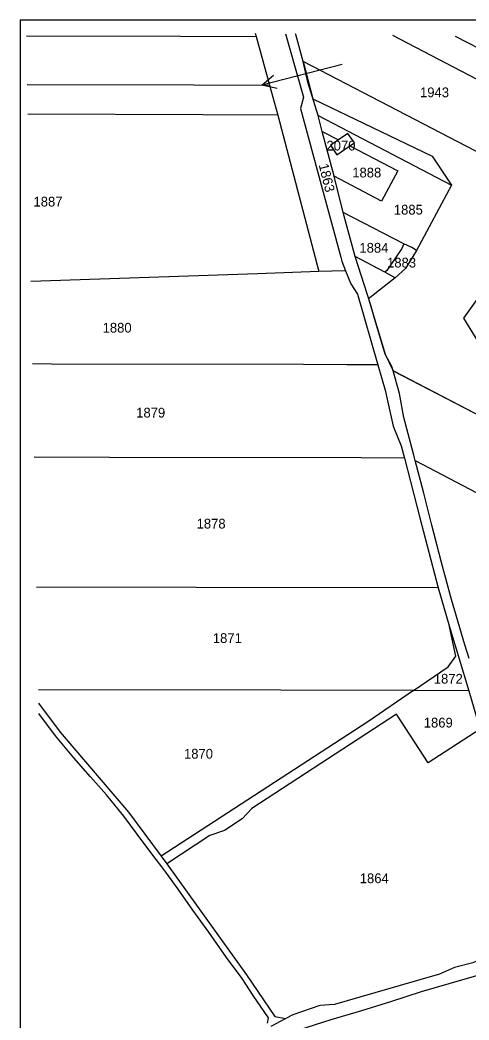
# Model space of a CAD drawing. Extents: x -584305 to -582773, y -1166873 to -1164754.
# Drawn here: x -584305 to -583983, y -1165491 to -1164773 of the extents above; entities that cross this region are included whole.
import ezdxf

# ---------------------------------------------------------------- set-up
doc = ezdxf.new("R2010")
doc.units = 0
for name, color, linetype in [('37', 7, 'Continuous'), ('_Rám HC11-R', 7, 'Continuous'), ('Hranice parcel', 7, 'Continuous'), ('Parcelní čísla', 7, 'Continuous')]:
    doc.layers.add(name, color=color, linetype=linetype)

msp = doc.modelspace()

# ---------------------------------------------------------------- linework, layer by layer
at = {"layer": '37'}
msp.add_line((-584073.78, -1164805.07), (-584131.38, -1164819.91), dxfattribs=at)
msp.add_lwpolyline([(-584120.54, -1164822.24), (-584131.38, -1164819.91), (-584123.02, -1164812.64)], dxfattribs=at)
at = {"layer": '_Rám HC11-R'}
msp.add_lwpolyline([(-582820.03, -1166873.12), (-582820.03, -1164773.12), (-584305.03, -1164773.12), (-584305.03, -1166873.12), (-582820.03, -1166873.12)], dxfattribs=at)
msp.add_lwpolyline([(-583928.98, -1165081.35), (-583986.49, -1164987.28), (-583967.99, -1164961.13), (-583954.85, -1164923.82), (-583942.36, -1164931.66), (-583924.13, -1164896.6), (-583941.58, -1164886.27), (-584101.83, -1164802.98), (-584094.81, -1164829.69), (-584009.27, -1164870.93), (-583995.35, -1164891.63), (-584020.43, -1164938.66), (-584028.48, -1164951.62), (-584035.7, -1164958.26), (-584055.06, -1164973.28), (-584042.99, -1165013.09), (-584037.3, -1165024.95)], close=True, dxfattribs=at)
at = {"layer": 'Hranice parcel'}
for p, q in [((-584136.29, -1164782.6), (-584135.64, -1164784.94)), ((-584135.64, -1164784.94), (-584126.01, -1164819.84)), ((-583956.67, -1164826.46), (-584037.5, -1164784.25)), ((-583947.23, -1164808.23), (-583992.46, -1164785)), ((-584126.01, -1164819.84), (-584120.06, -1164841.33)), ((-584120.06, -1164841.33), (-584090.48, -1164953.81)), ((-584088.14, -1164853.24), (-584091.16, -1164841.68)), ((-584079.67, -1164885.17), (-584088.14, -1164853.24)), ((-584088.14, -1164853.24), (-584076.59, -1164859.25)), ((-584073.2, -1164911.26), (-584079.67, -1164885.17)), ((-584064.56, -1164942.96), (-584073.2, -1164911.26)), ((-584029.68, -1164933.86), (-584073.2, -1164911.26)), ((-584043.31, -1164954.22), (-584064.56, -1164942.96)), ((-584071.34, -1164953.16), (-584090.48, -1164953.81)), ((-583928.98, -1165081.35), (-584037.3, -1165024.95)), ((-584004.96, -1165180.89), (-583996.84, -1165208.83)), ((-583996.84, -1165208.83), (-583983.04, -1165254.67)), ((-583983.04, -1165254.67), (-584022.77, -1165254.58)), ((-584203.2, -1165381.2), (-584207.26, -1165375.81)), ((-584203.74, -1165373.5), (-584199.68, -1165378.89)), ((-584114.38, -1165490.11), (-584125.04, -1165495.82))]:
    msp.add_line(p, q, dxfattribs=at)
for points in [[(-584114.4, -1164782.96), (-584112.02, -1164791.38), (-584101.48, -1164828.6), (-584103.83, -1164836.55), (-584088.97, -1164891.37), (-584074.9, -1164943.28), (-584074.11, -1164946.18), (-584071.34, -1164953.16)], [(-584101.83, -1164802.98), (-584107.21, -1164783.62), (-584107.33, -1164783.08)], [(-584300.45, -1164784.58), (-584189.89, -1164784.82), (-584135.64, -1164784.94)], [(-584091.16, -1164841.68), (-584098.46, -1164817.69), (-584101.83, -1164802.98)], [(-583924.13, -1164896.6), (-583941.58, -1164886.27), (-584101.83, -1164802.98)], [(-584299.81, -1164819.45), (-584180.12, -1164819.72), (-584126.01, -1164819.84)], [(-584120.06, -1164841.33), (-584173.88, -1164841.17), (-584299.42, -1164840.8)], [(-584091.16, -1164841.68), (-583995.35, -1164891.63), (-584020.43, -1164938.66)], [(-584068.32, -1164863.56), (-584065.1, -1164861.38), (-584069.75, -1164854.62), (-584076.59, -1164859.25)], [(-584076.59, -1164859.25), (-584082.28, -1164863.1), (-584077.69, -1164869.91), (-584068.32, -1164863.56)], [(-584068.32, -1164863.56), (-584033.99, -1164881.43), (-584045.57, -1164903.16), (-584079.67, -1164885.17)], [(-584029.68, -1164933.86), (-584030.98, -1164937.12), (-584041.73, -1164953.04), (-584043.31, -1164954.22)], [(-584020.43, -1164938.66), (-584023.92, -1164936.53), (-584029.68, -1164933.86)], [(-584020.43, -1164938.66), (-584028.48, -1164951.62), (-584035.7, -1164958.26), (-584043.31, -1164954.22)], [(-584037.3, -1165024.95), (-584038.16, -1165021.95), (-584042.99, -1165013.09), (-584050.52, -1164988.21), (-584053.61, -1164977.12), (-584064.56, -1164942.96)], [(-584090.48, -1164953.81), (-584134.71, -1164955.31), (-584297.22, -1164960.82)], [(-584071.34, -1164953.16), (-584067.63, -1164962.48), (-584062.83, -1164970.07), (-584048.18, -1165020.65)], [(-584048.18, -1165020.65), (-584070.46, -1165020.6), (-584101.61, -1165020.53), (-584282.43, -1165020.13), (-584296.13, -1165020.1)], [(-584048.18, -1165020.65), (-584042.91, -1165038.81), (-584037.18, -1165064.8), (-584031.46, -1165078.76), (-584029.16, -1165087.65)], [(-584021.34, -1165089.39), (-584022.33, -1165085.67), (-584029.5, -1165058.59), (-584032.63, -1165041.29), (-584037.3, -1165024.95)], [(-584029.16, -1165087.65), (-584060.23, -1165087.58), (-584240.73, -1165087.18), (-584294.91, -1165087.06)], [(-584029.16, -1165087.65), (-584018.01, -1165130.6), (-584004.96, -1165180.89)], [(-583982.63, -1165231.56), (-583985.75, -1165221.62), (-583995.35, -1165189.21), (-584002.45, -1165162.55), (-584009.56, -1165135.88), (-584015.15, -1165112.74), (-584021.34, -1165089.39)], [(-584021.34, -1165089.39), (-583953, -1165125.34), (-583904.11, -1165151.07)], [(-584004.96, -1165180.89), (-584178.59, -1165180.51), (-584293.2, -1165180.26)], [(-584022.77, -1165254.58), (-583997.85, -1165237.48), (-583992.24, -1165229.99), (-583996.84, -1165208.83)], [(-584022.77, -1165254.58), (-584117.85, -1165254.37), (-584291.84, -1165253.99)], [(-584022.77, -1165254.58), (-584055.51, -1165277.05), (-584203.74, -1165373.5)], [(-583983.04, -1165254.67), (-583977.35, -1165273.76), (-583974.84, -1165282.18)], [(-584291.66, -1165263.71), (-584276.18, -1165284.38), (-584227.24, -1165341.86), (-584203.74, -1165373.5)], [(-584207.26, -1165375.81), (-584216.08, -1165364.12), (-584230.46, -1165344.81), (-584242.87, -1165329.46), (-584254.33, -1165316.55), (-584266.48, -1165302.89), (-584279.48, -1165286.98), (-584291.53, -1165271.1)], [(-583974.84, -1165282.18), (-584012.07, -1165306.46), (-584034.84, -1165271.61), (-584138.63, -1165339.21), (-584145.7, -1165346.69), (-584158.2, -1165355.08), (-584168.81, -1165358.7), (-584199.68, -1165378.89)], [(-583974.84, -1165282.18), (-583954.94, -1165348.93), (-583952.24, -1165368.22), (-583945.43, -1165383.61), (-583944.47, -1165391.31), (-583943.78, -1165404.8), (-583949.92, -1165432.02), (-583955.76, -1165438.7), (-583979.99, -1165450.08), (-583993.12, -1165453.3), (-584003.91, -1165458.08), (-584032.27, -1165466.39), (-584079.46, -1165479.88), (-584089.8, -1165480.66), (-584109.32, -1165487.31), (-584114.38, -1165490.11)], [(-584199.68, -1165378.89), (-584142.41, -1165458.77), (-584122.2, -1165488.62), (-584114.38, -1165490.11)], [(-584127.54, -1165493.29), (-584126.7, -1165489.49), (-584137.68, -1165473.5), (-584145.63, -1165461.29), (-584156.82, -1165446.27), (-584169.56, -1165428.1), (-584181.07, -1165412.34), (-584191.49, -1165397.12), (-584200.37, -1165384.95), (-584203.2, -1165381.2)], [(-583953.93, -1165452.64), (-583988.32, -1165462.57), (-584017.19, -1165470.76), (-584039.23, -1165478.13), (-584060.02, -1165484.43), (-584082.01, -1165490.99), (-584105.29, -1165498.3), (-584107.56, -1165499.38), (-584111.74, -1165503.97), (-584113.23, -1165508.57)]]:
    msp.add_lwpolyline(points, dxfattribs=at)

# ---------------------------------------------------------------- texts
at = {"layer": 'Parcelní čísla'}
for s, p in [('1943', (-584017.98, -1164828.56)), ('2070', (-584085.15, -1164866.83)), ('1888', (-584066.61, -1164886.15)), ('1887', (-584295.36, -1164907.03)), ('1885', (-584036.77, -1164912.81)), ('1884', (-584061.48, -1164940.17)), ('1883', (-584041.63, -1164950.82)), ('1880', (-584245.76, -1164997.55)), ('1879', (-584221.65, -1165058.53)), ('1878', (-584178.31, -1165138.23)), ('1871', (-584166.65, -1165220.4)), ('1872', (-584008.09, -1165249.59)), ('1869', (-584015.3, -1165281.1)), ('1870', (-584187.36, -1165303.44)), ('1864', (-584061.22, -1165392.86))]:
    msp.add_text(s, height=7, dxfattribs=at).set_placement(p)
msp.add_text('1863', height=7, rotation=284, dxfattribs=at).set_placement((-584090.76, -1164877.13))

doc.saveas('drawing.dxf')
